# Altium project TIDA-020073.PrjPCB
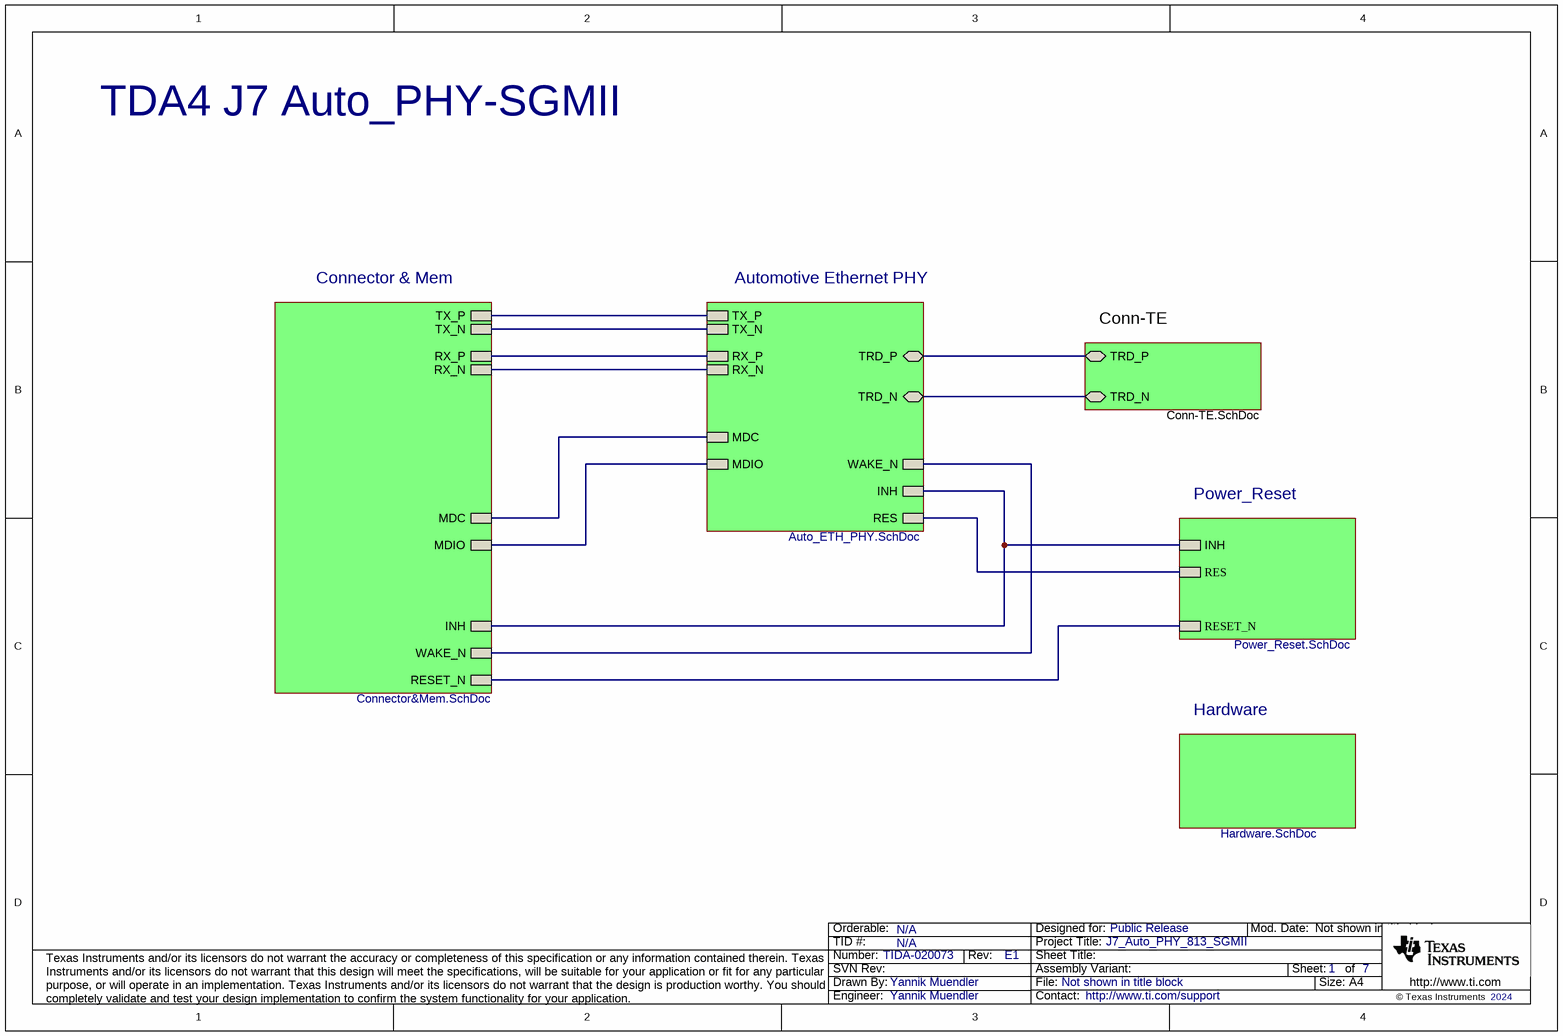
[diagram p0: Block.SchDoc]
CopyrightYear: 2024; DrawnBy: Yannik Muendler; EVM_orderable: N/A; PCB_Layout: Yannik Muendler; PCB_Rev: E1; PRJ_Customer: Public Release; PRJ_Engineer: Yannik Muendler; PRJ_Number: TIDA-020073; PRJ_Title: J7_Auto_PHY_813_SGMII; SCH_Rev: E1; TechSupport: http://www.ti.com/support; TID: N/A
6 sheets, 145 parts. Net scope: hierarchical (ports join the sheet entries above them; power ports are global).
Board file: TIDA-020073.PcbDoc
Sheets:
  Block.SchDoc
    Conn-TE = Conn-TE.SchDoc
    Connector & Mem = Connector&Mem.SchDoc
    Automotive Ethernet PHY = Auto_ETH_PHY.SchDoc
    Hardware = Hardware.SchDoc
    Power_Reset = Power_Reset.SchDoc

## Sheet Block.SchDoc
size A4; Date: Not shown in title block; ApprovedBy: Not shown in title block; CheckedBy: Not shown in title block; Author: Not shown in title block; CompanyName: Not shown in title block; Engineer: Not shown in title block; Organization: Not shown in title block; Address1: Not shown in title block; Address2: Not shown in title block; Address3: Not shown in title block; Address4: Not shown in title block; DocumentNumber: 1; Revision: Use project parameter SCH_Rev; SheetNumber: 1; SheetTotal: 7; PageSetup: Record=PageOptions¦CenterHorizontal=True¦CenterVertical=True¦PrintScale=0.93¦XCorrection=1.00¦YCorrection=1.00¦PrintKind=0¦BorderSize=5000000¦LeftOffset=0¦BottomOffset=0¦Orientation=2¦PaperLength=1000¦PaperWidth=1000¦Scale=100¦PaperSource=15¦PrintQuality=600¦MediaType=1¦DitherType=10¦PaperKind=Letter¦PrintScaleMode=1

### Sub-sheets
Automotive Ethernet PHY = Auto_ETH_PHY.SchDoc: TRD_P (bidir), TRD_N (bidir), RES, WAKE_N, MDIO, MDC, INH, TX_P, TX_N, RX_P, RX_N
Conn-TE = Conn-TE.SchDoc: TRD_P (bidir), TRD_N (bidir)
Connector & Mem = Connector&Mem.SchDoc: WAKE_N, RESET_N, INH, TX_P, TX_N, RX_P, RX_N, MDIO, MDC
Hardware = Hardware.SchDoc: no entries
Power_Reset = Power_Reset.SchDoc: INH, RESET_N, RES

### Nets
INH: sheet Connector & Mem/INH, sheet Automotive Ethernet PHY/INH, sheet Power_Reset/INH
MDC: sheet Connector & Mem/MDC, sheet Automotive Ethernet PHY/MDC
MDIO: sheet Connector & Mem/MDIO, sheet Automotive Ethernet PHY/MDIO
RESET: sheet Automotive Ethernet PHY/RES, sheet Power_Reset/RES
RESET_N: sheet Connector & Mem/RESET_N, sheet Power_Reset/RESET_N
RX_N: sheet Connector & Mem/RX_N, sheet Automotive Ethernet PHY/RX_N
RX_P: sheet Connector & Mem/RX_P, sheet Automotive Ethernet PHY/RX_P
TRD1_N: sheet Conn-TE/TRD_N, sheet Automotive Ethernet PHY/TRD_N
TRD1_P: sheet Conn-TE/TRD_P, sheet Automotive Ethernet PHY/TRD_P
TX_N: sheet Connector & Mem/TX_N, sheet Automotive Ethernet PHY/TX_N
TX_P: sheet Connector & Mem/TX_P, sheet Automotive Ethernet PHY/TX_P
WAKE_N: sheet Connector & Mem/WAKE_N, sheet Automotive Ethernet PHY/WAKE_N

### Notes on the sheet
- TDA4 J7 Auto_PHY-SGMII

## Sheet Conn-TE.SchDoc
size A4; Date: Not shown in title block; ApprovedBy: Not shown in title block; CheckedBy: Not shown in title block; Author: Not shown in title block; CompanyName: Not shown in title block; Engineer: Not shown in title block; Organization: Not shown in title block; Address1: Not shown in title block; Address2: Not shown in title block; Address3: Not shown in title block; Address4: Not shown in title block; DocumentNumber: 1; Revision: Use project parameter SCH_Rev; SheetNumber: 4; SheetTotal: 7; PageSetup: Record=PageOptions¦CenterHorizontal=True¦CenterVertical=True¦PrintScale=1.00¦XCorrection=1.00¦YCorrection=1.00¦PrintKind=0¦BorderSize=5000000¦LeftOffset=0¦BottomOffset=0¦Orientation=2¦PaperLength=1000¦PaperWidth=1000¦Scale=100¦PaperSource=15¦PrintQuality=600¦MediaType=1¦DitherType=10¦PaperKind=Letter¦PrintScaleMode=1
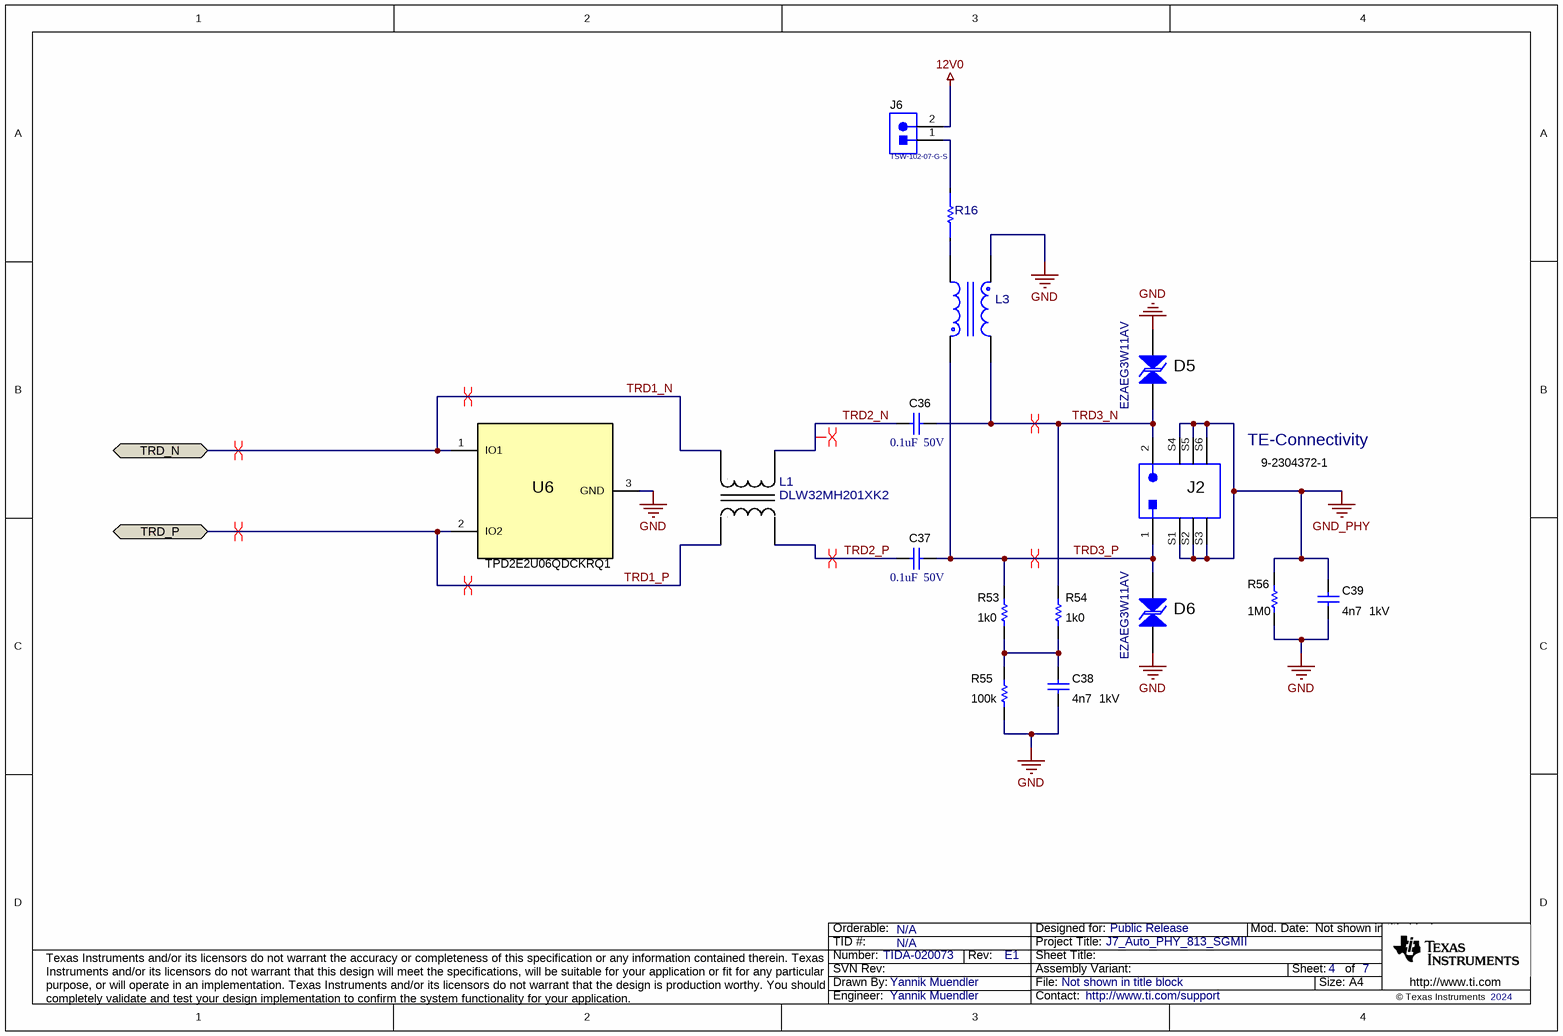
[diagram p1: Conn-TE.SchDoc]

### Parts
C36  VDC_V: 50V  ValueDisplayed: 0.1uF  [0402S]  (hidden comment: C1005X5R1H104K050BB)
C37  VDC_V: 50V  ValueDisplayed: 0.1uF  [0402S]  (hidden comment: C1005X5R1H104K050BB)
C38  VDC_V: 1kV  ValueDisplayed: 4n7  [1206]  (hidden comment: GRM31BR73A472KW01L)
C39  VDC_V: 1kV  ValueDisplayed: 4n7  [1206]  (hidden comment: GRM31BR73A472KW01L)
D5  EZAEG3W11AV  [0603]
D6  EZAEG3W11AV  [0603]
J2  9-2304372-1  Supplier 1: TE-Connectivity  [TE_1PORT_B1-B]
J6  TSW-102-07-G-S  [TSW-102-07-G-S]
L1  DLW32MH201XK2  [FP-DLW32MH201XK2_1210-MFG]
L3  ADL32VHR-180M  [FP-ADL32VHR-180M_SMT_3MM2_2MM5-MFG]  (value not drawn)
R16  CRCW06030000Z0EAC  [FP-CRCW06030000Z0EAC_0603-MFG]  (value not drawn)
R53  ValueDisplayed: 1k0  [0805_HV]  (hidden comment: ERJ-P06F1001V)
R54  ValueDisplayed: 1k0  [0805_HV]  (hidden comment: ERJ-P06F1001V)
R55  ValueDisplayed: 100k  [0805_HV]  (hidden comment: RT0805BRD07100KL)
R56  ValueDisplayed: 1M0  [1206]  (hidden comment: CRCW12061M00JNEA)
U6  TPD2E2U06QDCKRQ1  [DCK0003A_N]

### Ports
TRD_N (bidir), TRD_P (bidir)

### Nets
12V0: J6.2
GND: C38.2 C39.2 D5.2 D6.1 L3.3 R55.1 R56.2 U6.3(GND)
GND_PHY: C39.1 J2.S1(GND) J2.S2(GND) J2.S3(GND) J2.S4(GND) J2.S5(GND) J2.S6(GND) R56.1
TRD1_N: L1.4 U6.1(IO1) ; port TRD_N
TRD1_P: L1.1 U6.2(IO2) ; port TRD_P
TRD2_N: C36.2 L1.3
TRD2_P: C37.2 L1.2
TRD3_N: C36.1 D5.1 J2.2 L3.4 R54.2
TRD3_P: C37.1 D6.2 J2.1 L3.1 R53.2
NetC38_1: C38.1 R53.1 R54.1 R55.2
NetJ6_1: J6.1 R16.2
NetL3_2: L3.2 R16.1

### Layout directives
differential pair: TRD1_N, TRD1_P, TRD2_N, TRD2_P, TRD3_N, TRD3_P

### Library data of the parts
C36 C37 = CMP-0006279-2: CAP, CERM, 0.1 uF, 50 V, +/- 10%, X5R, 0402; Manufacturer: TDK; TaMin_C: -55°C; Polarized: N; SizeAreaWB_mm2: 3; Value1: 0.039064 ohm; U/M: EA; Value: 0.1uF; TaMax_C: 85°C; SizeZ_mm: 0.6; SizeX_mm: 1; SizeY_mm: 0.5; Cap_Case: 0402; Cap_F: 100nF; AEC Category: Q200; ESR_ohm: 39.064m; IRMS_A: 814.669mA
C38 C39 = CMP-0008920-2: CAP, CERM, 4700 pF, 1000 V, +/- 10%, X7R, 1206; Manufacturer: MuRata; TaMin_C: -55°C; Polarized: N; SizeAreaWB_mm2: 10.92; Value1: Unknown; U/M: EA; Value: 4700pF; TaMax_C: 125°C; SizeZ_mm: 1.35; SizeX_mm: 3.2; SizeY_mm: 1.6; Value2: 1000V; SizeArea_mm2: 5.12; Cap_F: 4.7nF; AEC Category: Q200
D5 D6 = CMP-0086344-1: Diode, TVS, Bi, AEC-Q101, 0603; Manufacturer: Panasonic; SizeX_mm: 1.6; AEC Qualified: Y; SizeArea_mm2: 1.28; SizeY_mm: 0.8; SizeAreaWB_mm2: 4.68; AEC Category: Q101; SizeZ_mm: 1
J2 = CMP-0054903-1: Header(shrouded), 2x1, R/A, TH; Manufacturer: TE Connectivity; Gender: Male; Pitch_mm: 1.8; CT: FALSE; Row_Count: 1; Shrouded: Y
J6 = CMP-0075405-3: Header, 100mil, 2x1, Gold, TH; Manufacturer: Samtec; Pitch_mm: 2.54; Cert_VDE: N; Gender: Male; Cert_CSA: Y; Voltage_V: 550V; Green_REACh: Passed; Current_A: 6.3A; Green_Lifecycle: Active; Row_Count: 1
L1 = CMP-0087001-1: 200µH @ 100kHz 2 Line Common Mode Choke Surface Mount 70mA DCR 4.8 Ohm; Manufacturer: Murata; AEC Qualified: Yes; SizeZ_mm: 2.5mm; AEC Grade: Grade 1
L3 = CMP-0122302-1: Differential Mode Choke 18uH 370mA 0.84Ohm 3.2x2.5x2.5mm SMT; Manufacturer: TDK; DCR_ohm: 0.84; Ind_H: 18µH; SizeZ_mm: 2.5mm; AEC Qualified: No; AEC Grade: Grade 0; Test Frequency: 100kHz; TJmax_C: +150°C; Tolerance_%: 20%
R16 = CMP-0094742-1: CRCW Series 0603 0.1 W 0 Ohm Jumper Surface Mount Thick Film Chip Resistor; Manufacturer: Vishay; Category 7542B8484461Ae85: Passive Components; SizeZ_mm: 0.55mm; VDC_V: 75V; AEC Qualified: No; Category Cd01000Bfc2916C6: Single Components; Value: 0; Category 5C6A91606D4187Ad: Resistors; Power_W: 100mW
R53 R54 = CMP-0021848-2: RES, 1.00 k, 1%, 0.25 W, 0805; Manufacturer: Panasonic; Power_W: 250mW; TempCo: 100 ppm/C; Value_Code: 1k00; U/M: EA; Value: 1.00k; EIA_Code: E96; Res_ohm: 1k; SizeX_mm: 2; SizeY_mm: 1.25; SizeZ_mm: 1.45; Value2: 0.25W; SizeArea_mm2: 2.5; VDC_V: 400V; AEC Category: Q200
R55 = CMP-0019441-2: RES, 100 k, 0.1%, 0.125 W, 0805; Manufacturer: Yageo America; Power_W: 125mW; TempCo: 25 ppm/C; U/M: EA; Value: 100k; EIA_Code: E192; SizeX_mm: 2; SizeY_mm: 1.25; SizeZ_mm: 1.45; Value2: 0.125W; SizeArea_mm2: 2.5; VDC_V: 150V; AEC Category: Q200
R56 = CMP-0018610-3: RES, 1.0 M, 5%, 0.25 W, AEC-Q200 Grade 0, 1206; Manufacturer: Vishay-Dale; Power_W: 250mW; TempCo: 200 ppm/C; Value_Code: 1M00; Value: 1.0Meg; EIA_Code: E24; Res_ohm: 1M; SizeX_mm: 3.2; SizeY_mm: 1.6; SizeZ_mm: 1.35; Value2: 0.25W; SizeArea_mm2: 5.12; AEC Qualified: Y; VDC_V: 200V; AEC Category: Q200; AEC Grade: 0
U6 = CMP-0073595-1: Automotive Dual-Channel High-Speed ESD Protection Device, DCK0003A (SOT-SC70-3); Alternate Manufacturer: Texas Instruments; SizeAreaWB_mm2: 9.3; U/M: EA; SizeZ_mm: 1.1; SizeX_mm: 2.1; SizeY_mm: 2.0; SizeArea_mm2: 4.2; CompType: IC

## Sheet Connector&Mem.SchDoc
size A4; Date: Not shown in title block; ApprovedBy: Not shown in title block; CheckedBy: Not shown in title block; Author: Not shown in title block; CompanyName: Not shown in title block; Engineer: Not shown in title block; Organization: Not shown in title block; Address1: Not shown in title block; Address2: Not shown in title block; Address3: Not shown in title block; Address4: Not shown in title block; DocumentNumber: 3; Revision: Use project parameter SCH_Rev; SheetNumber: 2; SheetTotal: 7; PageSetup: Record=PageOptions¦CenterHorizontal=True¦CenterVertical=True¦PrintScale=1.00¦XCorrection=1.00¦YCorrection=1.00¦PrintKind=0¦BorderSize=5000000¦LeftOffset=0¦BottomOffset=0¦Orientation=2¦PaperLength=1000¦PaperWidth=1000¦Scale=100¦PaperSource=15¦PrintQuality=600¦MediaType=1¦DitherType=10¦PaperKind=Letter¦PrintScaleMode=1
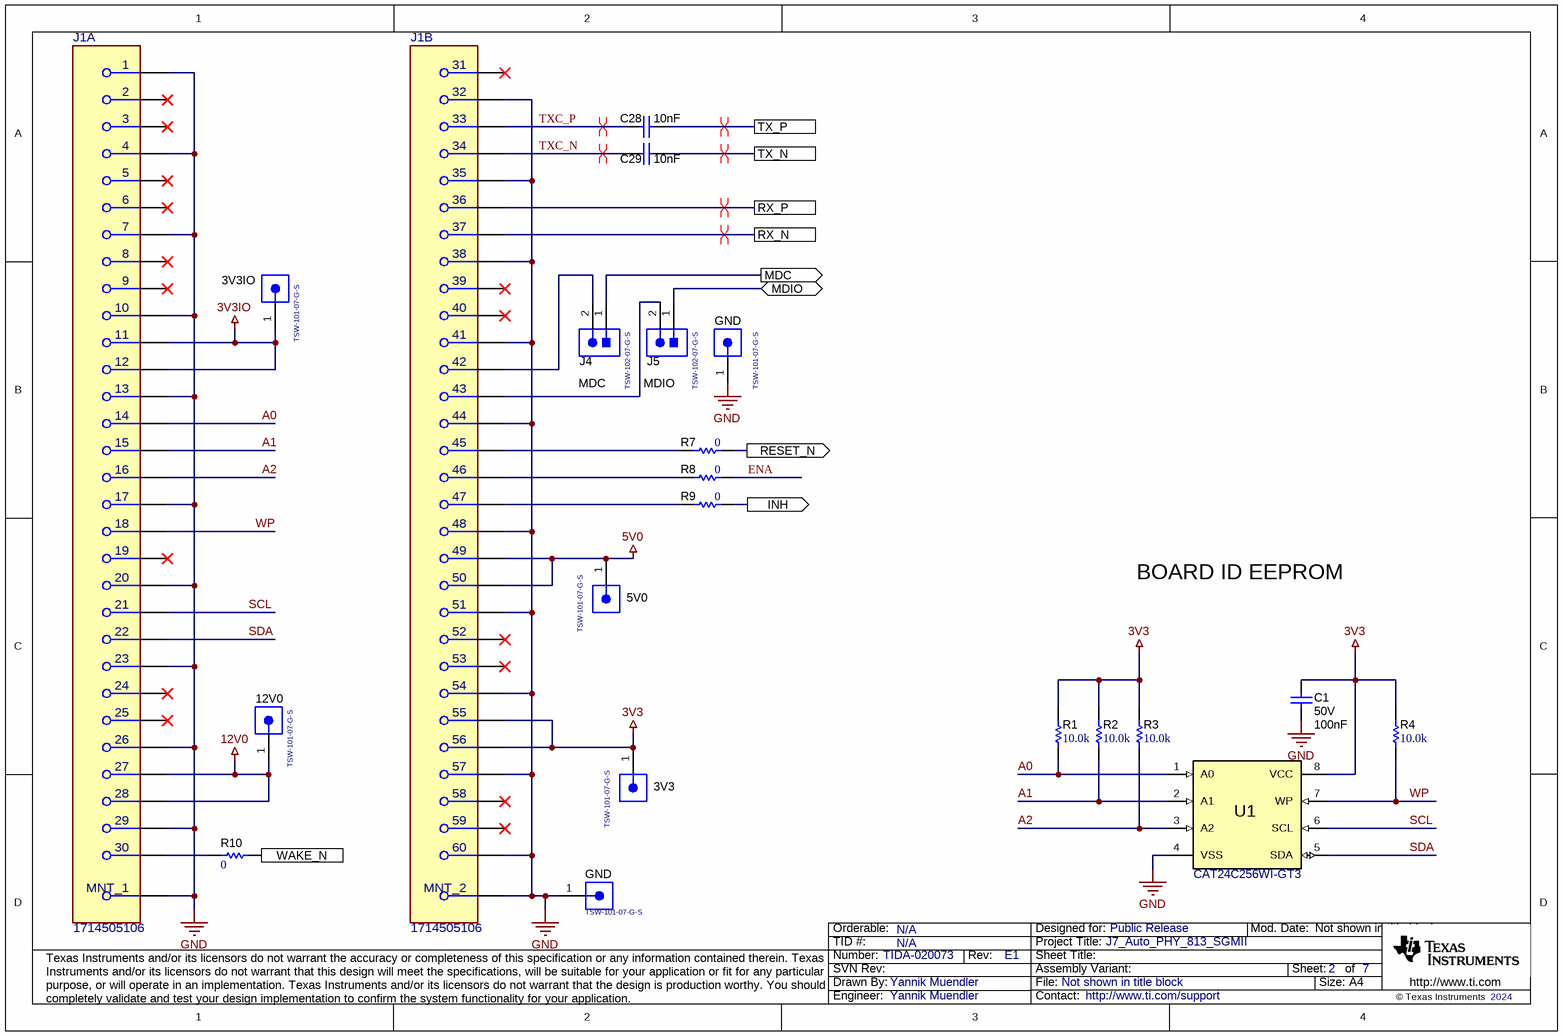
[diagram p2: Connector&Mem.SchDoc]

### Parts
(Parts that share a designator on the sheet are numbered #1, #2 ... from top to bottom, then left to right.)
3V3  TSW-101-07-G-S  [TSW-101-07-G-S]
3V3IO  TSW-101-07-G-S  [TSW-101-07-G-S]
5V0  TSW-101-07-G-S  [TSW-101-07-G-S]
12V0  TSW-101-07-G-S  [TSW-101-07-G-S]
C1  VDC_V: 50V  ValueDisplayed: 100nF  [0402]  (hidden comment: C1005X5R1H104K050BB)
C28  ValueDisplayed: 10nF  [0402S]  (hidden comment: GRM155R61C103KA01D)
C29  ValueDisplayed: 10nF  [0402S]  (hidden comment: GRM155R61C103KA01D)
GND#1  TSW-101-07-G-S  [TSW-101-07-G-S]
GND#2  TSW-101-07-G-S  [TSW-101-07-G-S]
J1  1714505106  [FP-1714505106_CONN_RCPT60-MFG]  (parts A,B of 2)
J4  TSW-102-07-G-S  [TSW-102-07-G-S]
J5  TSW-102-07-G-S  [TSW-102-07-G-S]
R1  ValueDisplayed: 10.0k  [0402]  (hidden comment: RT0402BRD0710KL)
R2  ValueDisplayed: 10.0k  [0402]  (hidden comment: RT0402BRD0710KL)
R3  ValueDisplayed: 10.0k  [0402]  (hidden comment: RT0402BRD0710KL)
R4  ValueDisplayed: 10.0k  [0402]  (hidden comment: RT0402BRD0710KL)
R7  ValueDisplayed: 0  [0402]  (hidden comment: CRCW04020000Z0ED)
R8  ValueDisplayed: 0  [0402]  (hidden comment: CRCW04020000Z0ED)
R9  ValueDisplayed: 0  [0402]  (hidden comment: CRCW04020000Z0ED)
R10  ValueDisplayed: 0  [0402]  (hidden comment: CRCW04020000Z0ED)
U1  CAT24C256WI-GT3  [SOIC-8]

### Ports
INH (out), MDC (out), MDIO (bidir), RESET_N (out), RX_N, RX_P, TX_N, TX_P, WAKE_N (out)

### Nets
3V3: 3V3.1 C1.2 J1.55 J1.56 R1.2 R2.2 R3.2 R4.2 U1.8(VCC)
3V3IO: 3V3IO.1 J1.11 J1.12
5V0: 5V0.1 J1.49 J1.50
12V0: 12V0.1 J1.27 J1.28
GND: C1.1 GND#1.1 GND#2.1 J1.1 J1.4 J1.7 J1.10 J1.13 J1.17 J1.20 J1.23 J1.26 J1.29 J1.32 J1.35 J1.38 J1.41 J1.44 J1.48 J1.51 J1.54 J1.57 J1.60 J1.61(MNT_1) J1.62(MNT_2) U1.4(VSS)
A0: J1.14 R1.1 U1.1(A0)
A1: J1.15 R2.1 U1.2(A1)
A2: J1.16 R3.1 U1.3(A2)
ENA: R8.1
INH: R9.1 ; port INH
MDC: J4.1 ; port MDC
MDIO: J5.1 ; port MDIO
RESET_N: R7.1 ; port RESET_N
RX_N: J1.37 ; port RX_N
RX_P: J1.36 ; port RX_P
SCL: J1.21 U1.6(SCL)
SDA: J1.22 U1.5(SDA)
TX_N: C29.2 ; port TX_N
TX_P: C28.2 ; port TX_P
TXC_N: C29.1 J1.34
TXC_P: C28.1 J1.33
WAKE_N: R10.2 ; port WAKE_N
WP: J1.18 R4.1 U1.7(WP)
NetJ1_30: J1.30 R10.1
NetJ1_42: J1.42 J4.2
NetJ1_43: J1.43 J5.2
NetJ1_45: J1.45 R7.2
NetJ1_46: J1.46 R8.2
NetJ1_47: J1.47 R9.2

Not connected (* = marked no-connect by the designer): J1 2* 3* 5* 6* 8* 9* 19* 24* 25* 31* 39* 40* 52* 53* 58* 59*

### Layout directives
differential pair: RX_N, RX_P, TX_N, TX_P, TXC_N, TXC_P

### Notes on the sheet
- (near J4) MDC
- MDIO
- BOARD ID EEPROM

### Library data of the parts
3V3 3V3IO 5V0 12V0 GND#1 GND#2 = CMP-0075403-1: Header, 100mil, 1pos, Gold, TH; Manufacturer: Samtec; Pitch_mm: 2.54; Cert_VDE: N; Gender: Male; Cert_CSA: Y; Voltage_V: 550V; Green_REACh: Passed; Current_A: 6.3A; CT: False; Green_Lifecycle: Active; Row_Count: 1; CNHeader: True
C1 = CMP-0006279-2: CAP, CERM, 0.1 uF, 50 V, +/- 10%, X5R, 0402; Manufacturer: TDK; TaMin_C: -55°C; ESR_ohm: 0.039064; Polarized: N; SizeAreaWB_mm2: 3; Value1: 0.039064 ohm; U/M: EA; Value: 0.1uF; TaMax_C: 85°C; SizeZ_mm: 0.6; SizeX_mm: 1; SizeY_mm: 0.5; IRMS_A: 814.669mA; AEC Category: Q200
C28 C29 = CMP-0006590-2: CAP, CERM, 0.01 uF, 16 V, +/- 10%, X5R, 0402; Manufacturer: MuRata; TaMin_C: -55°C; Polarized: N; SizeAreaWB_mm2: 3; Value1: Unknown; U/M: EA; Value: 0.01uF; TaMax_C: 85°C; SizeZ_mm: 0.6; SizeX_mm: 1; SizeY_mm: 0.5; Cap_Case: 0402; Value2: 16V; AEC Category: Q200
J1 = CMP-0122299-1: Conn Shrouded RCP 60 POS 0.8mm Solder ST SMD Emboss T/R; Manufacturer: Molex; ContactFinish: Gold,Nickel; Current_A: 800mA; Row_Count: 2; Voltage_V: 29.9V; AEC Qualified: No; Conn Gender: Female; Conn Orientation: Vertical; Is Female: yes; SizeZ_mm: 4.98mm
J4 J5 = CMP-0075405-3: as J6 on sheet Conn-TE
R1-R4 = CMP-0065360-1: RES, 10.0 k, .1%, .0625 W, 0402; Manufacturer: Yageo America; Power_W: 62.5mW; TempCo: 25 ppm/C; Value_Code: 10k0; Value: 10.0k; EIA_Code: E192; Tolerance_%: 0.1%; Res_ohm: 10k; SizeX_mm: 1.0; SizeY_mm: 0.5; SizeZ_mm: 0.6; Value2: .0625W; VDC_V: 50V; AEC Category: Q200; U/M: EA
R7-R10 = CMP-0026822-3: RES, 0, 5%, 0.063 W, AEC-Q200 Grade 0, 0402; Manufacturer: Vishay-Dale; AEC Qualified: Y; Value: 0; SizeZ_mm: 0.6; Power_W: 63mW; VDC_V: 50V; TempCo: 200 ppm/C; Value_Code: 0000; EIA_Code: E24; SizeX_mm: 1; SizeY_mm: 0.5; Value2: 0.063W; AEC Category: Q200
U1 = CMP-0005313-2: 256 kb I2C CMOS Serial EEPROM, SOIC-8; Manufacturer: ON Semiconductor; SizeAreaWB_mm2: 55.131; SizeZ_mm: 1.75; SizeX_mm: 5.99; SizeY_mm: 4.9; SizeArea_mm2: 29.351

## Sheet Auto_ETH_PHY.SchDoc
size A3; Date: Not shown in title block; ApprovedBy: Not shown in title block; CheckedBy: Not shown in title block; Author: Not shown in title block; CompanyName: Not shown in title block; Engineer: Not shown in title block; Organization: Not shown in title block; Address1: Not shown in title block; Address2: Not shown in title block; Address3: Not shown in title block; Address4: Not shown in title block; DocumentNumber: 2; Revision: Use project parameter SCH_Rev; SheetNumber: 3; SheetTotal: 7; PageSetup: Record=PageOptions¦CenterHorizontal=True¦CenterVertical=True¦PrintScale=1.00¦XCorrection=1.00¦YCorrection=1.00¦PrintKind=0¦BorderSize=5000000¦LeftOffset=0¦BottomOffset=0¦Orientation=2¦PaperLength=1000¦PaperWidth=1000¦Scale=100¦PaperSource=15¦PrintQuality=600¦MediaType=1¦DitherType=10¦PaperKind=Letter¦PrintScaleMode=1
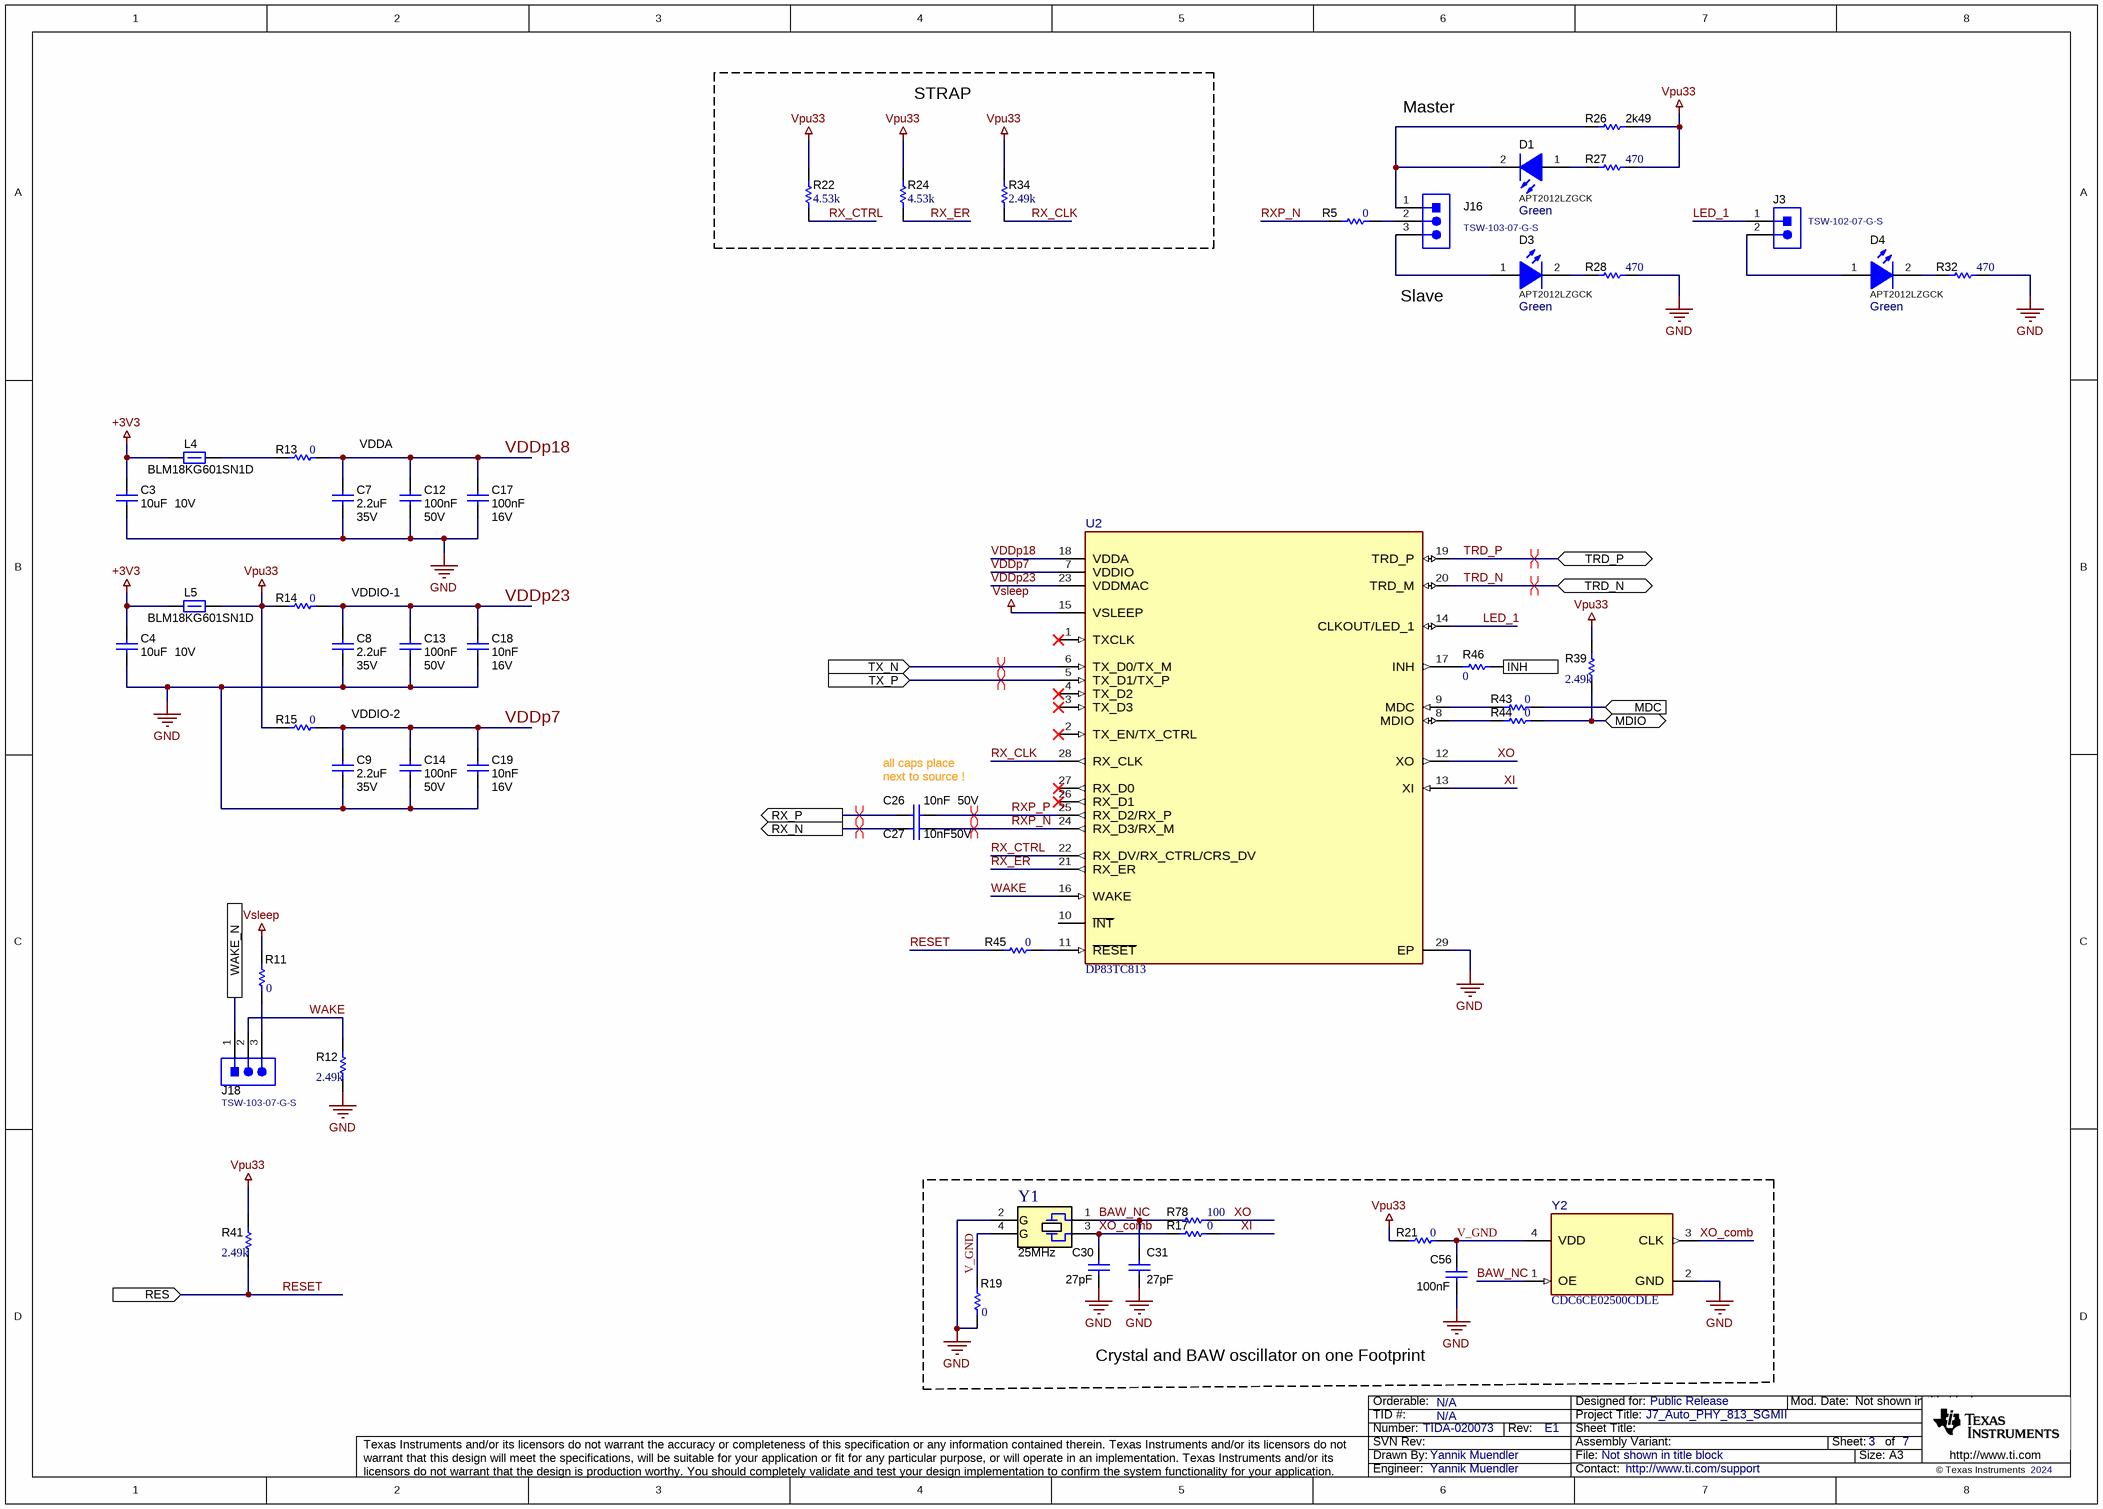
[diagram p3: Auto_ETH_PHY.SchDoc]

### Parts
C3  VDC_V: 10V  ValueDisplayed: 10uF  [0402]  (hidden comment: GRM155R61A106ME11)
C4  VDC_V: 10V  ValueDisplayed: 10uF  [0402]  (hidden comment: GRM155R61A106ME11)
C7  VDC_V: 35V  ValueDisplayed: 2.2uF  [0402_065]  (hidden comment: C1005X5R1V225K050BC)
C8  VDC_V: 35V  ValueDisplayed: 2.2uF  [0402_065]  (hidden comment: C1005X5R1V225K050BC)
C9  VDC_V: 35V  ValueDisplayed: 2.2uF  [0402_065]  (hidden comment: C1005X5R1V225K050BC)
C12  VDC_V: 50V  ValueDisplayed: 100nF  [0402]  (hidden comment: C1005X5R1H104K050BB)
C13  VDC_V: 50V  ValueDisplayed: 100nF  [0402]  (hidden comment: C1005X5R1H104K050BB)
C14  VDC_V: 50V  ValueDisplayed: 100nF  [0402]  (hidden comment: C1005X5R1H104K050BB)
C17  VDC_V: 16V  ValueDisplayed: 100nF  [0402]  (hidden comment: GRM155R61C103KA01D)
C18  VDC_V: 16V  ValueDisplayed: 10nF  [0402]  (hidden comment: GRM155R61C103KA01D)
C19  VDC_V: 16V  ValueDisplayed: 10nF  [0402]  (hidden comment: GRM155R61C103KA01D)
C26  VDC_V: 50V  ValueDisplayed: 10nF  [0402S]  (hidden comment: C1005X5R1H104K050BB)
C27  VDC_V: 50V  ValueDisplayed: 10nF  [0402S]  (hidden comment: C1005X5R1H104K050BB)
C30  ValueDisplayed: 27pF  [0402]  (hidden comment: C0402C270J5GACTU)
C31  ValueDisplayed: 27pF  [0402]  (hidden comment: C0402C270J5GACTU)
C56  ValueDisplayed: 100nF  [0402]  (hidden comment: C1005X5R1H104K050BB)
D1  APT2012LZGCK  value Green  [APT2012_Green]
D3  APT2012LZGCK  value Green  [APT2012_Green]
D4  APT2012LZGCK  value Green  [APT2012_Green]
J3  TSW-102-07-G-S  [TSW-102-07-G-S]
J16  TSW-103-07-G-S  [TSW-103-07-G-S]
J18  TSW-103-07-G-S  [TSW-103-07-G-S]
L4  BLM18KG601SN1D  [0603]
L5  BLM18KG601SN1D  [0603]
R5  ValueDisplayed: 0  [0402S]  (hidden comment: CRCW04020000Z0ED)
R11  ValueDisplayed: 0  [0402]  (hidden comment: CRCW04020000Z0ED)
R12  ValueDisplayed: 2.49k  [0402]  (hidden comment: CRCW04022K49FKED)
R13  ValueDisplayed: 0  [0402]  (hidden comment: CRCW04020000Z0ED)
R14  ValueDisplayed: 0  [0402]  (hidden comment: CRCW04020000Z0ED)
R15  ValueDisplayed: 0  [0402]  (hidden comment: CRCW04020000Z0ED)
R17  ValueDisplayed: 0  [0402S]  (hidden comment: CRCW04020000Z0ED)
R19  ValueDisplayed: 0  [0402]  (hidden comment: CRCW04020000Z0ED)
R21  ValueDisplayed: 0  [0402]  (hidden comment: CRCW04020000Z0ED)
R22  ValueDisplayed: 4.53k  [0402]  (hidden comment: CRCW04024K53FKED)
R24  ValueDisplayed: 4.53k  [0402]  (hidden comment: CRCW04024K53FKED)
R26  ValueDisplayed: 2k49  [0402]  (hidden comment: CRCW04022K49FKED)
R27  ValueDisplayed: 470  [0402]  (hidden comment: CRCW0402470RJNED)
R28  ValueDisplayed: 470  [0402]  (hidden comment: CRCW0402470RJNED)
R32  ValueDisplayed: 470  [0402]  (hidden comment: CRCW0402470RJNED)
R34  ValueDisplayed: 2.49k  [0402]  (hidden comment: CRCW04022K49FKED)
R39  ValueDisplayed: 2.49k  [0402]  (hidden comment: CRCW04022K49FKED)
R41  ValueDisplayed: 2.49k  [0402]  (hidden comment: CRCW04022K49FKED)
R43  ValueDisplayed: 0  [0402]  (hidden comment: CRCW04020000Z0ED)
R44  ValueDisplayed: 0  [0402]  (hidden comment: CRCW04020000Z0ED)
R45  ValueDisplayed: 0  [0402]  (hidden comment: CRCW04020000Z0ED)
R46  ValueDisplayed: 0  [0402]  (hidden comment: CRCW04020000Z0ED)
R78  ValueDisplayed: 100  [0402S]  (hidden comment: CRCW0402100RFKED)
U2  DP83TC813  [RHF0028A-MFG]
Y1  Frequency_Fixed: 25MHz  [Abracon_ABM8AIG]  (hidden comment: ABM8AIG-25.000MHZ-12-2Z-T3)
Y2  CDC6CE02500CDLE  [DLE0004A-MFG]

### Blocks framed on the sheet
STRAP: R22 R24 R34
Crystal and BAW oscillator on one Footprint: C30 C31 C56 R17 R19 R21 R78 Y1 Y2

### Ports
INH (out), MDC (in), MDIO (bidir), RES (in), RX_N (out), RX_P (out), TRD_N (bidir), TRD_P (bidir), TX_N (in), TX_P (in), WAKE_N

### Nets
+3V3: C3.1 C4.1 L4.1 L5.1
GND: C3.2 C4.2 C7.2 C8.2 C9.2 C12.1 C13.1 C14.1 C17.2 C18.2 C19.2 C30.2 C31.2 C56.1 R12.1 R19.1 R28.1 R32.1 U2.29(EP) Y1.2(GND) Y2.2(GND)
Vpu33: L5.2 R14.2 R15.2 R21.2 R22.1 R24.1 R26.2 R27.1 R34.1 R39.2 R41.2
Vsleep: R11.2 U2.15(VSLEEP)
BAW_NC: C31.1 R78.2 Y1.1 Y2.1(OE)
INH: R46.2 ; port INH
LED_1: J3.1 U2.14(CLKOUT/LED_1)
MDC: R43.2 ; port MDC
MDIO: R39.1 R44.2 ; port MDIO
RESET: R41.1 R45.2 ; port RES
RX_CLK: R34.2 U2.28(RX_CLK)
RX_CTRL: R22.2 U2.22(RX_DV/RX_CTRL/CRS_DV)
RX_ER: R24.2 U2.21(RX_ER)
RX_N: C27.1 ; port RX_N
RX_P: C26.1 ; port RX_P
RXP_N: C27.2 R5.2 U2.24(RX_D3/RX_M)
RXP_P: C26.2 U2.25(RX_D2/RX_P)
TRD_N: U2.20(TRD_M) ; port TRD_N  [project net TRD1_N]
TRD_P: U2.19(TRD_P) ; port TRD_P  [project net TRD1_P]
TX_N: U2.6(TX_D0/TX_M) ; port TX_N
TX_P: U2.5(TX_D1/TX_P) ; port TX_P
V_GND: C56.2 R19.2 R21.1 Y1.4(GND) Y2.4(VDD)
VDDp7: C9.1 C14.2 C19.1 R15.1 U2.7(VDDIO)
VDDp18: C7.1 C12.2 C17.1 R13.1 U2.18(VDDA)
VDDp23: C8.1 C13.2 C18.1 R14.1 U2.23(VDDMAC)
WAKE: J18.2 R12.2 U2.16(WAKE)
WAKE_N: J18.1 ; port WAKE_N
XI: R17.1 U2.13(XI)
XO: R78.1 U2.12(XO)
XO_comb: C30.1 R17.2 Y1.3 Y2.3(CLK)
NetD1_1: D1.1(A) R27.2
NetD1_2: D1.2(K) J16.1 R26.1
NetD3_1: D3.1(A) J16.3
NetD3_2: D3.2(K) R28.2
NetD4_1: D4.1(A) J3.2
NetD4_2: D4.2(K) R32.2
NetJ16_2: J16.2 R5.1
NetJ18_3: J18.3 R11.1
NetL4_2: L4.2 R13.2
NetR43_1: R43.1 U2.9(MDC)
NetR44_1: R44.1 U2.8(MDIO)
NetR45_1: R45.1 U2.11(~{RESET})
NetR46_1: R46.1 U2.17(INH)

Not connected (* = marked no-connect by the designer): U2 1(TXCLK)* 2(TX_EN/TX_CTRL)* 3(TX_D3)* 4(TX_D2)* 10(~{INT}) 26(RX_D1)* 27(RX_D0)*

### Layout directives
differential pair: RX_N, RX_P, RXP_N, RXP_P, TRD1_N, TRD1_P, TX_N, TX_P

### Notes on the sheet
- Master
- Slave
- VDDA
- VDDIO-1
- VDDIO-2
- all caps place next to source !

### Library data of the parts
C3 C4 = CMP-0006564-2: CAP, CERM, 10 uF, 10 V, +/- 20%, X5R, 0402; Manufacturer: MuRata; TaMin_C: -55°C; Polarized: N; SizeAreaWB_mm2: 3; Value1: Unknown; U/M: EA; Value: 10uF; TaMax_C: 85°C; SizeZ_mm: 0.6; SizeX_mm: 1; SizeY_mm: 0.5; Cap_F: 10µF; AEC Category: Q200
C7-C9 = CMP-0006283-2: CAP, CERM, 2.2 uF, 35 V, +/- 10%, X5R, 0402; Manufacturer: TDK; TaMin_C: -55°C; ESR_ohm: 5.925m; Polarized: N; SizeAreaWB_mm2: 3; Value1: 0.005925 ohm; U/M: EA; Value: 2.2uF; TaMax_C: 85°C; SizeZ_mm: 0.65; SizeX_mm: 1; SizeY_mm: 0.5; Cap_F: 2.2µF; IRMS_A: 2.05591A; AEC Category: Q200
C12-C14 = CMP-0006279-2: CAP, CERM, 0.1 uF, 50 V, +/- 10%, X5R, 0402; Manufacturer: TDK; TaMin_C: -55°C; ESR_ohm: 39.064m; Polarized: N; SizeAreaWB_mm2: 3; Value1: 0.039064 ohm; U/M: EA; Value: 0.1uF; TaMax_C: 85°C; SizeZ_mm: 0.6; SizeX_mm: 1; SizeY_mm: 0.5; IRMS_A: 814.669mA; AEC Category: Q200
C17 = CMP-0006590-2: CAP, CERM, 0.01 uF, 16 V, +/- 10%, X5R, 0402; Manufacturer: MuRata; TaMin_C: -55°C; Polarized: N; SizeAreaWB_mm2: 3; Value1: Unknown; U/M: EA; Value: 0.01uF; TaMax_C: 85°C; SizeZ_mm: 0.6; SizeX_mm: 1; SizeY_mm: 0.5; Cap_F: 10nF; AEC Category: Q200
C18 C19 = CMP-0006590-2: CAP, CERM, 0.01 uF, 16 V, +/- 10%, X5R, 0402; Manufacturer: MuRata; TaMin_C: -55°C; Polarized: N; SizeAreaWB_mm2: 3; Value1: Unknown; U/M: EA; Value: 0.01uF; TaMax_C: 85°C; SizeZ_mm: 0.6; SizeX_mm: 1; SizeY_mm: 0.5; AEC Category: Q200
C26 C27 = CMP-0006279-2: CAP, CERM, 0.1 uF, 50 V, +/- 10%, X5R, 0402; Manufacturer: TDK; TaMin_C: -55°C; ESR_ohm: 39.064m; Polarized: N; SizeAreaWB_mm2: 3; Value1: 0.039064 ohm; U/M: EA; Value: 0.1uF; TaMax_C: 85°C; SizeZ_mm: 0.6; SizeX_mm: 1; SizeY_mm: 0.5; Cap_Case: 0402; Cap_F: 100nF; IRMS_A: 814.669mA; AEC Category: Q200
C30 C31 = CMP-0750098-1: CAP, CERM, 27 pF, 50 V,+/- 5%, C0G/NP0, 0402; Manufacturer: Kemet; SizeX_mm: 1; TaMin_C: -55°C; Value: 27pF; Polarized: N; SizeAreaWB_mm2: 3; SizeArea_mm2: 0.5; Green_REACh: Passed; Green_Lifecycle: Active; Value2: 50V; U/M: EA; AEC Category: Q200; SizeZ_mm: 0.6; TaMax_C: 125°C
C56 = CMP-0006279-2: CAP, CERM, 0.1 uF, 50 V, +/- 10%, X5R, 0402; Manufacturer: TDK; TaMin_C: -55°C; ESR_ohm: 0.039064; Polarized: N; SizeAreaWB_mm2: 3; Value1: 0.039064 ohm; U/M: EA; Value: 0.1uF; TaMax_C: 85°C; SizeZ_mm: 0.6; SizeX_mm: 1; SizeY_mm: 0.5; Value2: 50V; IRMS_A: 814.669mA; AEC Category: Q200
D1 D3 D4 = CMP-0002953-3: LED, Green, SMD; Manufacturer: Kingbright; Vr_V: 5V; Value2: 2.65V; Ir_A: 50µA; Angle: 120; Tjmax_C: 85°C; Type: InGaN; Power_TotalModule: 75mW; Io_A: 2mA; Value1: 0.075W
J3 = CMP-0075405-3: as J6 on sheet Conn-TE
J16 J18 = CMP-0075407-2: Header, 100mil, 3x1, Gold, TH; Manufacturer: Samtec; Pitch_mm: 2.54; Cert_VDE: N; Gender: Male; Cert_CSA: Y; Voltage_V: 550V; Green_REACh: Passed; Current_A: 6.3A; Green_Lifecycle: Active; Row_Count: 1
L4 = CMP-0003351-2: Ferrite Bead, 600 ohm @ 100 MHz, 1.3 A, 0603; Manufacturer: MuRata; ZTyp@100MHz_Ohm: 600; SizeAreaWB_mm2: 4.68; DCR_ohm: 0.15; Value1: 0.15 ohm; Value: 600 ohm; Imax_A: 1.3A; SizeZ_mm: 1; SizeX_mm: 1.6; SizeY_mm: 0.8; SizeArea_mm2: 1.28
L5 = CMP-0003351-2: Ferrite Bead, 600 ohm @ 100 MHz, 1.3 A, 0603; Manufacturer: MuRata; SizeAreaWB_mm2: 4.68; SizeArea_mm2: 1.28; Value: 600 ohm; SizeZ_mm: 1; Imax_A: 1.3A; ZTyp@100MHz_Ohm: 600; SizeY_mm: 0.8; Value1: 0.15 ohm; DCR_ohm: 0.15; SizeX_mm: 1.6
R5 R11 R13-R15 R17 R19 R21 R43-R46 = CMP-0026822-3: as R7 on sheet Connector&Mem
R12 R39 R41 = CMP-0026237-2: RES, 2.49 k, 1%, 0.063 W, AEC-Q200 Grade 0, 0402; Manufacturer: Vishay-Dale; Power_W: 63mW; TempCo: 100 ppm/C; Value_Code: 2k49; Value: 2.49k; EIA_Code: E96; SizeX_mm: 1; SizeY_mm: 0.5; SizeZ_mm: 0.6; Value2: 0.063W; AEC Qualified: Y; VDC_V: 50V; AEC Category: Q200; AEC Grade: 0
R22 R24 = CMP-0026410-2: RES, 4.53 k, 1%, 0.063 W, AEC-Q200 Grade 0, 0402; Manufacturer: Vishay-Dale; Power_W: 63mW; TempCo: 100 ppm/C; Value_Code: 4k53; Value: 4.53k; SizeX_mm: 1; SizeY_mm: 0.5; SizeZ_mm: 0.6; Value2: 0.063W; AEC Qualified: Y; AEC Grade: 0; AEC Category: Q200; EIA_Code: E96; VDC_V: 50V
R26 = CMP-0026237-2: RES, 2.49 k, 1%, 0.063 W, AEC-Q200 Grade 0, 0402; Manufacturer: Vishay-Dale; Power_W: 63mW; TempCo: 100 ppm/C; Value: 2.49k; EIA_Code: E96; SizeX_mm: 1; SizeY_mm: 0.5; SizeZ_mm: 0.6; Value2: 0.063W; AEC Qualified: Y; VDC_V: 50V; AEC Category: Q200; AEC Grade: 0
R27 R28 R32 = CMP-0026934-3: RES, 470, 5%, 0.063 W, AEC-Q200 Grade 0, 0402; Manufacturer: Vishay-Dale; Power_W: 63mW; TempCo: 200 ppm/C; Value_Code: 470R; Value: 470; EIA_Code: E24; SizeX_mm: 1; SizeY_mm: 0.5; SizeZ_mm: 0.6; Value2: 0.063W; AEC Qualified: Y; VDC_V: 50V; AEC Category: Q200; AEC Grade: 0
R34 = CMP-0026237-2: RES, 2.49 k, 1%, 0.063 W, AEC-Q200 Grade 0, 0402; Manufacturer: Vishay-Dale; Power_W: 63mW; TempCo: 100 ppm/C; Value_Code: 2k49; Value: 2.49k; SizeX_mm: 1; SizeY_mm: 0.5; SizeZ_mm: 0.6; Value2: 0.063W; AEC Qualified: Y; AEC Grade: 0; AEC Category: Q200; EIA_Code: E96; VDC_V: 50V
R78 = CMP-0025951-3: RES, 100, 1%, 0.063 W, AEC-Q200 Grade 0, 0402; Manufacturer: Vishay-Dale; Power_W: 63mW; TempCo: 100 ppm/C; Value_Code: 100R; Value: 100; EIA_Code: E96; SizeX_mm: 1; SizeY_mm: 0.5; SizeZ_mm: 0.6; Value2: 0.063W; AEC Qualified: Y; VDC_V: 50V; AEC Category: Q200; AEC Grade: 0
U2 = CMP-0090093-1: TC-10 Compliant 100Base-T1 Automotive Ethernet PHY; Manufacturer: Texas Instruments; SizeZ_mm: 1mm; Interface: Ethernet,Other; TaMax_C: +125°C; AEC Grade: Grade 1; Max Supply Voltage: 3.63V; Data Rate: 100Mbits/s; TJmax_C: +150°C; Simplex Duplex: Full-Duplex; AEC Qualified: Yes; TaMin_C: -40°C; Standoff Height: 0mm; Number Of Channels: 1; Min Supply Voltage: 1.62V
Y1 = CMP-0004682-5: Crystal, 25 MHz, 12pF, AEC-Q200 Grade 1, SMD; Manufacturer: Abracon Corporation; TaMin_C: -40°C; Frequency Stability: 50 ppm; SizeAreaWB_mm2: 14.7; TaMax_C: 125°C; SizeZ_mm: 0.8; SizeX_mm: 2.5; SizeY_mm: 3.2; SizeArea_mm2: 8; AEC Category: Q200; AEC Grade: 1; AEC Qualified: Y
Y2 = CMP-0001498-1: Low Jitter, Low Power, LVCMOS Output, BAW Oscillator; Manufacturer: Texas Instruments; Min Supply Voltage: 1.62V; Frequency Stability: 20ppm; SizeZ_mm: 1mm; Standoff Height: 0mm; Max Supply Voltage: 3.63V; Frequency_Fixed: 25MHz; Max Supply Current: 5mA; AEC Qualified: Yes; AEC Grade: Grade 1

## Sheet Hardware.SchDoc
size A4; Date: Not shown in title block; ApprovedBy: Not shown in title block; CheckedBy: Not shown in title block; Author: Not shown in title block; CompanyName: Not shown in title block; Engineer: Not shown in title block; Organization: Not shown in title block; Address1: Not shown in title block; Address2: Not shown in title block; Address3: Not shown in title block; Address4: Not shown in title block; DocumentNumber: 1; Revision: Use project parameter SCH_Rev; SheetNumber: 7; SheetTotal: 7; PageSetup: Record=PageOptions¦CenterHorizontal=True¦CenterVertical=True¦PrintScale=1.00¦XCorrection=1.00¦YCorrection=1.00¦PrintKind=0¦BorderSize=5000000¦LeftOffset=0¦BottomOffset=0¦Orientation=2¦PaperLength=1000¦PaperWidth=1000¦Scale=100¦PaperSource=15¦PrintQuality=600¦MediaType=1¦DitherType=10¦PaperKind=Letter¦PrintScaleMode=1
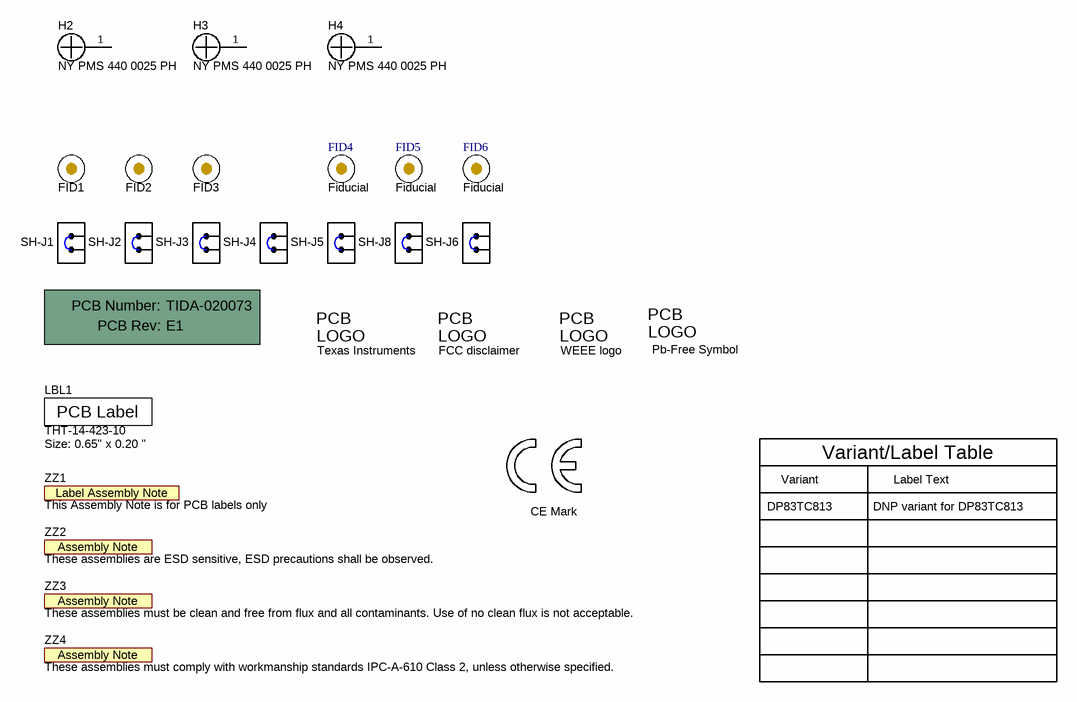
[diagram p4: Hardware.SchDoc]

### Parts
!PCB  Printed Circuit Board  (value not drawn)  (mechanical)
FID1  Fiducial  [Fiducial10-20]  (value not drawn)
FID2  Fiducial  [Fiducial10-20]  (value not drawn)
FID3  Fiducial  [Fiducial10-20]  (value not drawn)
FID4  Fiducial  [Fiducial10-30]
FID5  Fiducial  [Fiducial10-30]
FID6  Fiducial  [Fiducial10-30]
H2  NY PMS 440 0025 PH  [NY PMS 440 0025 PH]
H3  NY PMS 440 0025 PH  [NY PMS 440 0025 PH]
H4  NY PMS 440 0025 PH  [NY PMS 440 0025 PH]
LBL1  THT-14-423-10  Note: Size: 0.65" x 0.20 "  [Label_650x200]
Logo1  Texas Instruments  [TI_Stacked_Overlay_Small]  (no BOM)
Logo2  FCC disclaimer  [FCC_disclaimer]  (no BOM)
Logo3  WEEE logo  [WEEE_Minimum]  (no BOM)
Logo4  Pb-Free Symbol  [Pb-Free_Overlay_Small]  (no BOM)
Logo5  CE Mark  [CE_Mark_5mm]  (no BOM)
SH-J1  SPC02SYAN  [SPC02SYAN]  (value not drawn)
SH-J2  SPC02SYAN  [SPC02SYAN]  (value not drawn)
SH-J3  SPC02SYAN  [SPC02SYAN]  (value not drawn)
SH-J4  SPC02SYAN  [SPC02SYAN]  (value not drawn)
SH-J5  SPC02SYAN  [SPC02SYAN]  (value not drawn)
SH-J6  SPC02SYAN  [SPC02SYAN]  (value not drawn)
SH-J8  SPC02SYAN  [SPC02SYAN]  (value not drawn)
ZZ1  This Assembly Note is for PCB labels only  [AssemblyNoteLabel]  (no BOM)
ZZ2  These assemblies are ESD sensitive, ESD precautions shall be observed.  [AssemblyNote]  (no BOM)
ZZ3  These assemblies must be clean and free from flux and all contaminants. Use of no clean flux is not acceptable.  [AssemblyNote]  (no BOM)
ZZ4  These assemblies must comply with workmanship standards IPC-A-610 Class 2, unless otherwise specified.  [AssemblyNote]  (no BOM)

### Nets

Not connected (* = marked no-connect by the designer): H2 1; H3 1; H4 1

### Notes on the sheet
- Variant/Label Table
- Variant
- DP83TC813
- Label Text
- DNP variant for DP83TC813

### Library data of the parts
!PCB = CMP-0003618-2: Manufacturer: Any; PartNumber: TIDA-020073
FID1-FID6 = CMP-0077181-1: Fiducial mark.  There is nothing to buy or mount.
H2-H4 = CMP-0003617-1: Machine Screw, Round, #4-40 x 1/4, Nylon, Philips panhead; Manufacturer: B&F Fastener Supply; CompType: Hardware
LBL1 = CMP-0003625-1: Thermal Transfer Printable Labels, 0.650" W x 0.200" H - 10,000 per roll; Manufacturer: Brady; CompType: Label
Logo1 = CMP-0074838-1: Texas Instrument Corporate Signature; SymbolCreator: a0412235; Lib Reference: TI_Logo; Library Reference: Logo
Logo2 = CMP-0074847-1: FCC_disclaimer; Library Reference: Logo
Logo3 = CMP-0074769-3: Manufacturer: Texas Instruments; AEC Category: Q200; CompType: IC
Logo4 = CMP-0074839-1: Library Reference: Logo; SymbolCreator: a0412235
Logo5 = CMP-0074844-1: SymbolCreator: a0412235
SH-J1-SH-J6 SH-J8 = CMP-0003642-1: Shunt, 100mil, Flash Gold, Black; Manufacturer: Sullins Connector Solutions; Value: 1x2; Note: You can "mate" this to a header by matching the designator.  i.e. use SH-J3 for header J3
ZZ1 = CMP-0003616-3
ZZ2 = CMP-0077236-1
ZZ3 = CMP-0077237-1
ZZ4 = CMP-0077238-1

## Sheet Power_Reset.SchDoc
size A3; Date: Not shown in title block; ApprovedBy: Not shown in title block; CheckedBy: Not shown in title block; Author: Not shown in title block; CompanyName: Not shown in title block; Engineer: Not shown in title block; Organization: Not shown in title block; Address1: Not shown in title block; Address2: Not shown in title block; Address3: Not shown in title block; Address4: Not shown in title block; DocumentNumber: 2; Revision: Use project parameter SCH_Rev; SheetNumber: 5; SheetTotal: 7; PageSetup: Record=PageOptions¦CenterHorizontal=True¦CenterVertical=True¦PrintScale=1.00¦XCorrection=1.00¦YCorrection=1.00¦PrintKind=0¦BorderSize=5000000¦LeftOffset=0¦BottomOffset=0¦Orientation=2¦PaperLength=1000¦PaperWidth=1000¦Scale=100¦PaperSource=15¦PrintQuality=600¦MediaType=1¦DitherType=10¦PaperKind=Letter¦PrintScaleMode=1
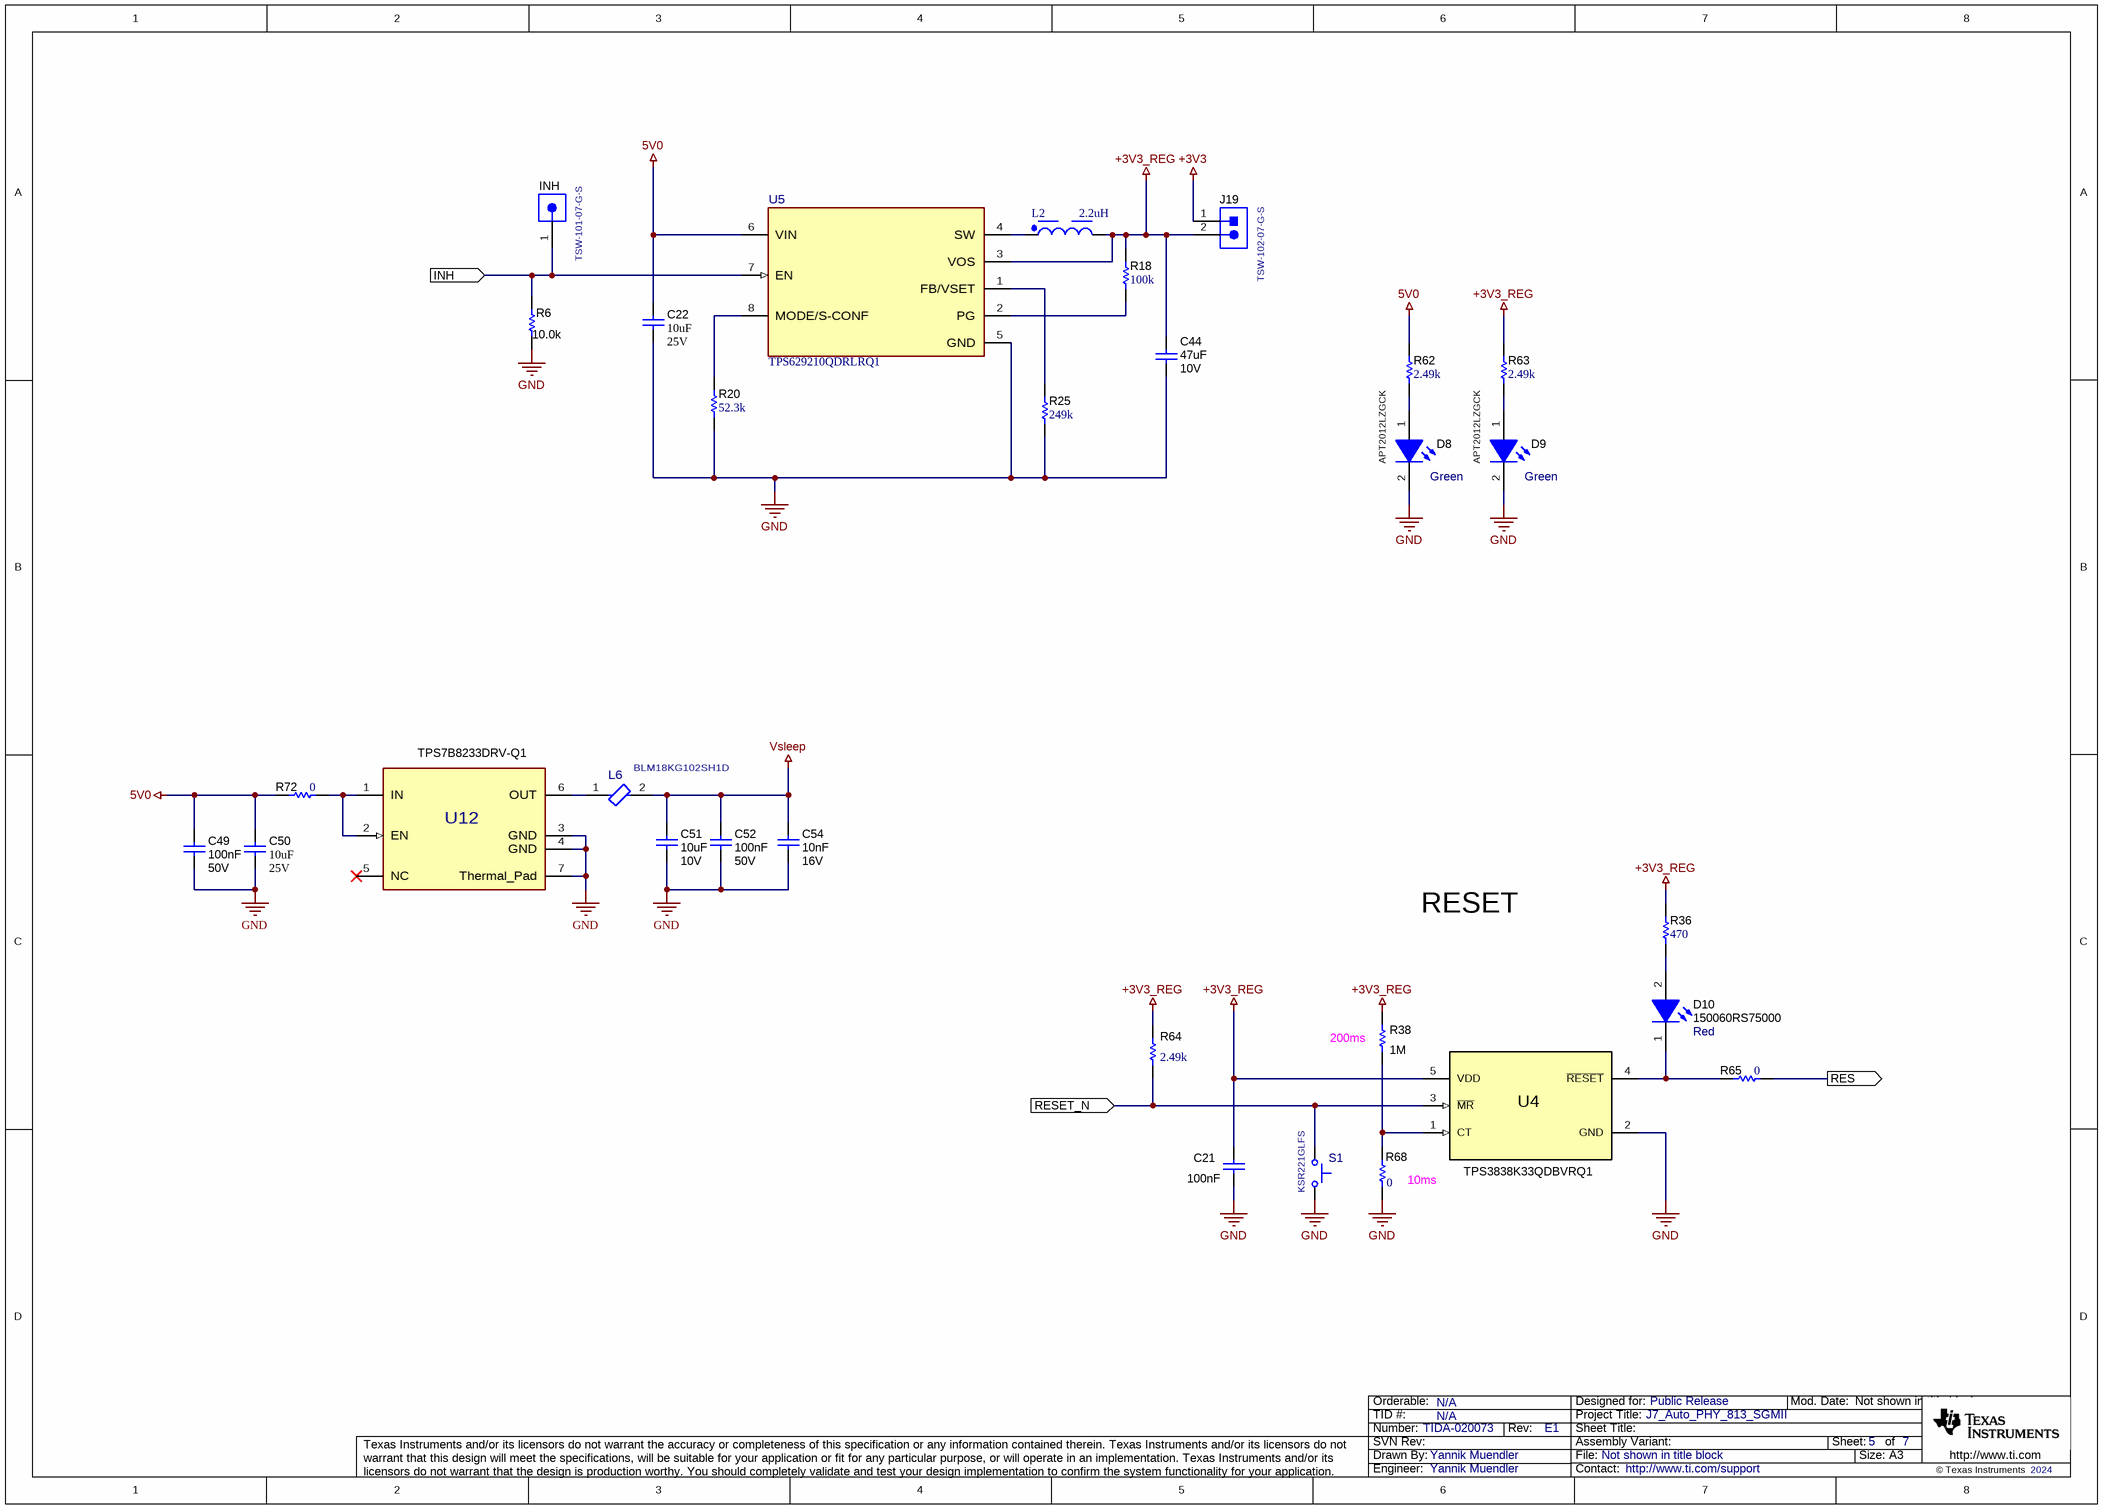
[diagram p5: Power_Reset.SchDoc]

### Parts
C21  ValueDisplayed: 100nF  [0402]  (hidden comment: C1005X5R1H104K050BB)
C22  VDC_V: 25V  ValueDisplayed: 10uF  [0603]  (hidden comment: C1608X5R1E106M080AC)
C44  VDC_V: 10V  ValueDisplayed: 47uF  [0805_HV]  (hidden comment: C2012X5R1A476M125AC)
C49  VDC_V: 50V  ValueDisplayed: 100nF  [0402]  (hidden comment: C1005X5R1H104K050BB)
C50  VDC_V: 25V  ValueDisplayed: 10uF  [0603]  (hidden comment: C1608X5R1E106M080AC)
C51  VDC_V: 10V  ValueDisplayed: 10uF  [0402]  (hidden comment: GRM155R61A106ME11)
C52  VDC_V: 50V  ValueDisplayed: 100nF  [0402]  (hidden comment: C1005X5R1H104K050BB)
C54  VDC_V: 16V  ValueDisplayed: 10nF  [0402]  (hidden comment: GRM155R61C103KA01D)
D8  APT2012LZGCK  value Green  [APT2012_Green]
D9  APT2012LZGCK  value Green  [APT2012_Green]
D10  150060RS75000  value Red  [WL-SMCW_RED]
INH  TSW-101-07-G-S  [TSW-101-07-G-S]
J19  TSW-102-07-G-S  [TSW-102-07-G-S]
L2  Inductance: 2.2uH  [WE-MAPI_4020]  (hidden comment: 74438356022)
L6  BLM18KG102SH1D  [FP-BLM18KG102SH1D_0603-MFG]
R6  ValueDisplayed: 10.0k  [0402]  (hidden comment: RT0402BRD0710KL)
R18  ValueDisplayed: 100k  [0402]  (hidden comment: CRCW0402100KFKED)
R20  ValueDisplayed: 52.3k  [0402]  (hidden comment: CRCW040252K3FKED)
R25  ValueDisplayed: 249k  [0402]  (hidden comment: CRCW0402249KFKED)
R36  ValueDisplayed: 470  [0402]  (hidden comment: CRCW0402470RJNED)
R38  ValueDisplayed: 1M  [0402]  (hidden comment: ERJ-2RKF1004X)
R62  ValueDisplayed: 2.49k  [0402]  (hidden comment: CRCW04022K49FKED)
R63  ValueDisplayed: 2.49k  [0402]  (hidden comment: CRCW04022K49FKED)
R64  ValueDisplayed: 2.49k  [0402]  (hidden comment: CRCW04022K49FKED)
R65  ValueDisplayed: 0  [0402]  (hidden comment: CRCW04020000Z0ED)
R68  ValueDisplayed: 0  [0402]  (hidden comment: CRCW04020000Z0ED)
R72  ValueDisplayed: 0  [0402]  (hidden comment: CRCW04020000Z0ED)
S1  KSR221GLFS  [KSR]
U4  TPS3838K33QDBVRQ1  [DBV0005A_N]
U5  TPS629210QDRLRQ1  [DRL0008A-MFG]
U12  TPS7B8233DRV-Q1  [DRV0006A-MFG]

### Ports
INH (in), RES (out), RESET_N (in)

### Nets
5V0: C22.1 C49.1 C50.1 R62.2 R72.2 U5.6(VIN)
+3V3: J19.1
+3V3_REG: C21.1 C44.1 J19.2 L2.2 R18.2 R36.1 R38.1 R63.2 R64.2 U4.5(VDD) U5.3(VOS)
GND: C21.2 C22.2 C44.2 C49.2 C50.2 C51.2 C52.2 C54.2 D8.2(K) D9.2(K) R6.1 R20.1 R25.1 R68.1 S1.2 U4.2(GND) U5.5(GND) U12.3(GND) U12.4(GND) U12.7(Thermal_Pad)
Vsleep: C51.1 C52.1 C54.1 L6.2
INH: INH.1 R6.2 U5.7(EN) ; port INH
RESET: R65.2 ; port RES
RESET_N: R64.1 S1.1 U4.3(~{MR}) ; port RESET_N
NetD8_1: D8.1(A) R62.1
NetD9_1: D9.1(A) R63.1
NetD10_1: D10.1(K) R65.1 U4.4(~{RESET})
NetD10_2: D10.2(A) R36.2
NetL2_1: L2.1 U5.4(SW)
NetL6_1: L6.1 U12.6(OUT)
NetR18_1: R18.1 U5.2(PG)
NetR20_2: R20.2 U5.8(MODE/S-CONF)
NetR25_2: R25.2 U5.1(FB/VSET)
NetR38_2: R38.2 R68.2 U4.1(CT)
NetR72_1: R72.1 U12.1(IN) U12.2(EN)

Not connected (* = marked no-connect by the designer): U12 5(NC)*

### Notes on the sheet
- RESET
- (near R38) 200ms
- 10ms

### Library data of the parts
C21 = CMP-0006279-2: as C56 on sheet Auto_ETH_PHY
C22 C50 = CMP-0007007-5: CAP, CERM, 10 uF, 25 V, +/- 20%, X5R, 0603; Manufacturer: TDK; TaMin_C: -55°C; ESR_ohm: 4.639m; Polarized: N; SizeAreaWB_mm2: 4.68; Value1: 0.004639 ohm; U/M: EA; Value: 10uF; TaMax_C: 85°C; SizeZ_mm: 1; SizeX_mm: 1.6; SizeY_mm: 0.8; SizeArea_mm2: 1.28; Cap_F: 10µF; IRMS_A: 2.41407A; AEC Category: Q200
C44 = CMP-0007825-2: CAP, CERM, 47 uF, 10 V, +/- 20%, X5R, 0805; Manufacturer: TDK; TaMin_C: -55°C; ESR_ohm: 2.94m; Polarized: N; SizeAreaWB_mm2: 6.75; Value1: 0.00294 ohm; U/M: EA; Value: 47uF; TaMax_C: 85°C; SizeZ_mm: 1.45; SizeX_mm: 2; SizeY_mm: 1.25; Cap_Case: 0805; SizeArea_mm2: 2.5; Cap_F: 47µF; IRMS_A: 3.80451A; AEC Category: Q200
C49 C52 = CMP-0006279-2: as C12 on sheet Auto_ETH_PHY
C51 = CMP-0006564-2: as C3 on sheet Auto_ETH_PHY
C54 = CMP-0006590-2: as C18 on sheet Auto_ETH_PHY
D8 D9 = CMP-0002953-3: as D1 on sheet Auto_ETH_PHY
D10 = CMP-0002947-3: LED, Red, SMD; Manufacturer: Wurth Elektronik; Value1: 0.072W; Vf_V: 2V; Angle: 140; Tjmax_C: 85°C; Type: AlInGaP; Vr_V: 5V; Io_A: 30mA; Power_TotalModule: 72mW
INH = CMP-0075403-1: as 3V3 on sheet Connector&Mem
J19 = CMP-0075405-3: as J6 on sheet Conn-TE
L2 = CMP-0099146-1: WE-MAPI SMT Power Inductor, size 4020, 2.2uH, 4.7A, 35mOhm; Manufacturer: Wurth Elektronik; Case/Size Code: 4020; DC Resistance: 29mOhm; Saturation Current: 6.2A; Self Resonant Frequency: 34MHz
L6 = CMP-0089381-1: 1 kOhms @ 100MHz 1 Power Line Ferrite Bead 0603 (1608 Metric) 1A 200mOhm; Manufacturer: Murata; AEC Grade: Grade 1; AEC Qualified: Yes; DCR_ohm: 0.2; Impedance At Frequency: 1kΩ @ 100MHz; SizeZ_mm: 0.95mm; Tolerance_%: 25%
R6 = CMP-0065360-1: RES, 10.0 k, .1%, .0625 W, 0402; Manufacturer: Yageo America; Power_W: 62.5mW; TempCo: 25 ppm/C; Value_Code: 10k0; U/M: EA; Value: 10.0k; EIA_Code: E192; Tolerance_%: 0.1%; Res_ohm: 10k; SizeX_mm: 1.0; SizeY_mm: 0.5; SizeZ_mm: 0.6; Value2: .0625W; VDC_V: 50V; AEC Category: Q200
R18 = CMP-0025950-3: RES, 100 k, 1%, 0.063 W, AEC-Q200 Grade 0, 0402; Manufacturer: Vishay-Dale; Power_W: 63mW; TempCo: 100 ppm/C; Value: 100k; EIA_Code: E96; SizeX_mm: 1; SizeY_mm: 0.5; SizeZ_mm: 0.6; Value2: 0.063W; AEC Qualified: Y; VDC_V: 50V; AEC Category: Q200; AEC Grade: 0
R20 = CMP-0026441-2: RES, 52.3 k, 1%, 0.063 W, AEC-Q200 Grade 0, 0402; Manufacturer: Vishay-Dale; Power_W: 63mW; TempCo: 100 ppm/C; Value_Code: 52k3; Value: 52.3k; EIA_Code: E96; SizeX_mm: 1; SizeY_mm: 0.5; SizeZ_mm: 0.6; Value2: 0.063W; AEC Qualified: Y; VDC_V: 50V; AEC Category: Q200; AEC Grade: 0
R25 = CMP-0026193-2: RES, 249 k, 1%, 0.063 W, AEC-Q200 Grade 0, 0402; Manufacturer: Vishay-Dale; Power_W: 63mW; TempCo: 100 ppm/C; Value: 249k; EIA_Code: E96; SizeX_mm: 1; SizeY_mm: 0.5; SizeZ_mm: 0.6; Value2: 0.063W; AEC Qualified: Y; VDC_V: 50V; AEC Category: Q200; AEC Grade: 0
R36 = CMP-0026934-3: as R27 on sheet Auto_ETH_PHY
R38 = CMP-0026660-1: RES, 1.00 M, 1%, 0.1 W, 0402; Manufacturer: Panasonic; Power_W: 100mW; TempCo: 100 ppm/C; Value_Code: 1M00; U/M: EA; Value: 1.00Meg; EIA_Code: E96; SizeX_mm: 1; SizeY_mm: 0.5; SizeZ_mm: 0.6; Value2: 0.1W; VDC_V: 50V; AEC Category: Q200
R62-R64 = CMP-0026237-2: as R12 on sheet Auto_ETH_PHY
R65 R68 R72 = CMP-0026822-3: as R7 on sheet Connector&Mem
S1 = CMP-0002170-2: Switch, Normally open, 2.3N force, 200k operations, SMD; Manufacturer: C&K Components; CurrentRating_mA: 1.001kA; SwitchFunction: Off-Mom; Circuit: SPST Switch; VDC_V: 32V; PositionCount: 1
U4 = CMP-0074267-1: Nanopower Supervisory Circuits for Automotive, DBV0005A (SOT-23-5); Alternate Manufacturer: Texas Instruments; SizeAreaWB_mm2: 14.82; U/M: EA; SizeZ_mm: 1.45; SizeX_mm: 2.8; SizeY_mm: 2.9; SizeArea_mm2: 8.12; CompType: IC
U5 = CMP-0089687-1: 3-V to 17-V, Synchronous Buck Converters in 1.6 mm x 2.1 mm SOT583 Package; Manufacturer: Texas Instruments; AEC Qualified: Yes; Standoff Height: 0mm; Output Voltage: 0.4-5.5V; Nominal Supply Current: 8mA; SizeZ_mm: 0.6mm; Number Of Outputs: 1; TJmax_C: +150°C; Output Type: AdjustableProgrammable; Max Supply Voltage: 17V; Min Supply Voltage: 3V; Switching Frequency: 2.5MHz
U12 = CMP-0090846-1: 300-mA High-Voltage Ultralow-IQ Low-Dropout Regulator; Manufacturer: Texas Instruments; Min Supply Voltage: 3V; TJmax_C: +150°C; Output Type: Fixed; Nominal Supply Current: 1.9-2.7uA; Output Voltage: 3.3V; Accuracy Percentage: 1.5%; AEC Grade: Grade 1; Number Of Outputs: 1; TaMax_C: +125°C; Max Supply Voltage: 40V; Standoff Height: 0mm; TaMin_C: -40°C; SizeZ_mm: 0.8mm; AEC Qualified: Yes; Dropout Voltage: 730mV

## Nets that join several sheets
5V0: Connector&Mem (5V0.1 J1.49 J1.50), Power_Reset (6 pins)
12V0: Conn-TE (J6.2), Connector&Mem (12V0.1 J1.27 J1.28)
+3V3: Auto_ETH_PHY (C3.1 C4.1 L4.1 L5.1), Power_Reset (J19.1)
GND: Conn-TE (8 pins), Connector&Mem (26 pins), Auto_ETH_PHY (21 pins), Power_Reset (20 pins)
Vsleep: Auto_ETH_PHY (R11.2 U2.15), Power_Reset (C51.1 C52.1 C54.1 L6.2)
INH: Connector&Mem (R9.1), Auto_ETH_PHY (R46.2), Power_Reset (INH.1 R6.2 U5.7)
MDC: Connector&Mem (J4.1), Auto_ETH_PHY (R43.2)
MDIO: Connector&Mem (J5.1), Auto_ETH_PHY (R39.1 R44.2)
RESET: Auto_ETH_PHY (R41.1 R45.2), Power_Reset (R65.2)
RESET_N: Connector&Mem (R7.1), Power_Reset (R64.1 S1.1 U4.3)
RX_N: Connector&Mem (J1.37), Auto_ETH_PHY (C27.1)
RX_P: Connector&Mem (J1.36), Auto_ETH_PHY (C26.1)
TRD1_N: Conn-TE (L1.4 U6.1), Auto_ETH_PHY (U2.20)
TRD1_P: Conn-TE (L1.1 U6.2), Auto_ETH_PHY (U2.19)
TX_N: Connector&Mem (C29.2), Auto_ETH_PHY (U2.6)
TX_P: Connector&Mem (C28.2), Auto_ETH_PHY (U2.5)
WAKE_N: Connector&Mem (R10.2), Auto_ETH_PHY (J18.1)

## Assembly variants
DP83TC813: not fitted C2 C5 C6 C10 C11 C15 C16 C47 C48 C56 D5 D6 H2 H3 H4 L3 R4 R11 R12 R16 R21 R23 R25 R34 R35 R39 R47 R48 R70 R71 U1 Y2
